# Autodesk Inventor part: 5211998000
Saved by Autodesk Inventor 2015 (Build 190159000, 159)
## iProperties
Created: 2020-07
Part Number: 5211998000
Checked By: TraceParts S.A.
Material: Generic
Catalog Web Link: www.traceparts.com
Document SubType Name: Modeling
Designer: TraceParts
Density: 1 g/cm^3
Appearance: Default
Company: TraceParts S.A.
Author: TraceParts
REFERENCE: 5211998000
DESIGN: TDM-100 (220V 60) BRA RZ - 5211998000
SUPPLIER: Soler & Palau
TraceParts.PartNumber: 10-20122018-119657
TraceParts.PartTitle: TDM
TraceParts.InstanceId: 10-20122018-119657773FLR5ZWFZK83GI4O6VXBSX6
TraceParts.PartStatus: Published
TraceParts.PartVersion: 1.0.2
TRACEPARTS: TRACEPARTS
TraceParts.PartLanguage: en
TraceParts.ClassPath: SOLER_PALAU:10-20122018-119657
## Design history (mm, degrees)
feature "5211998000"
body "Solid1"
